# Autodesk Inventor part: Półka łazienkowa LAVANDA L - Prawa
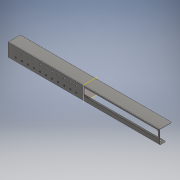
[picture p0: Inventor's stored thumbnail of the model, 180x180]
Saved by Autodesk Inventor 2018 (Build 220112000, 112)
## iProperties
Created: 2020-02
Part Number: Półka łazienkowa LAVANDA L - Prawa
Material: Ogólny
Document SubType Name: Modeling
Designer: Marcel
Density: 1 g/cm^3
Appearance: Domyślna
Author: Marcel
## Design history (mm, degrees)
derived "Półka łazienkowa LAVANDA L - Prawa.iam"
node "Bryła1"
node "Półka z uchwytem 1000 prawa.ipt:1"
node "Płaszczyzna konstrukcyjna1"
node "Kapselek.ipt:1"
node "Kapselek.ipt:2"
node "Kapselek.ipt:3"
